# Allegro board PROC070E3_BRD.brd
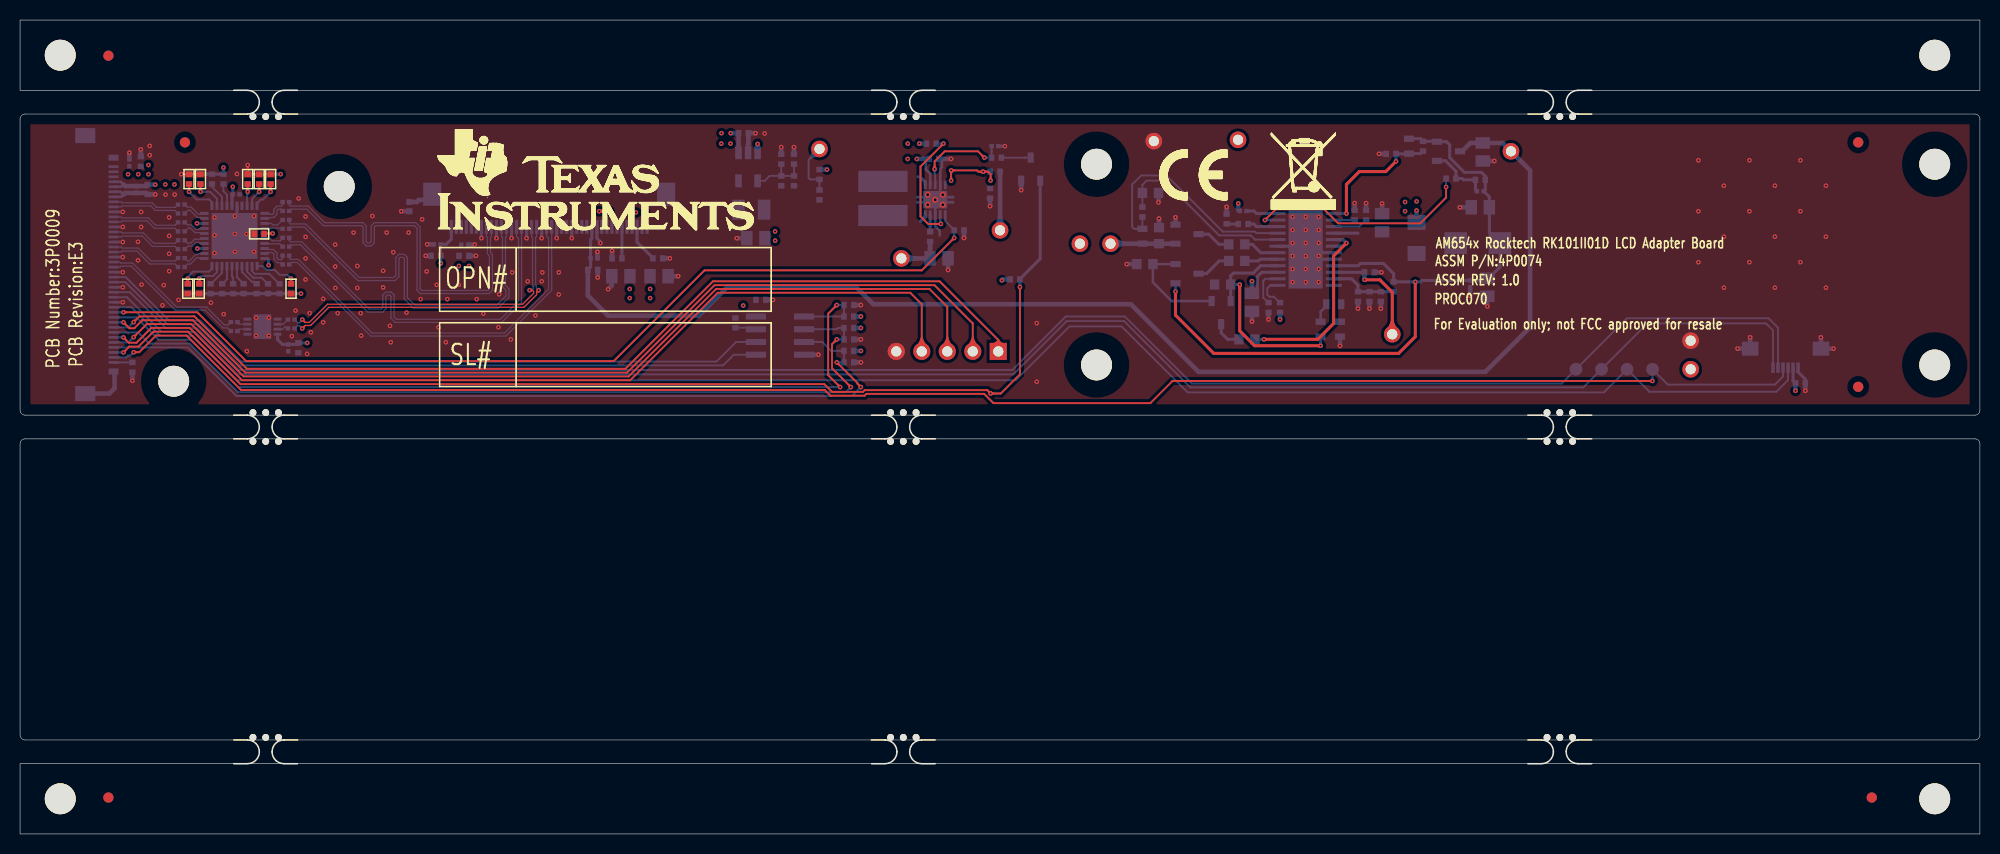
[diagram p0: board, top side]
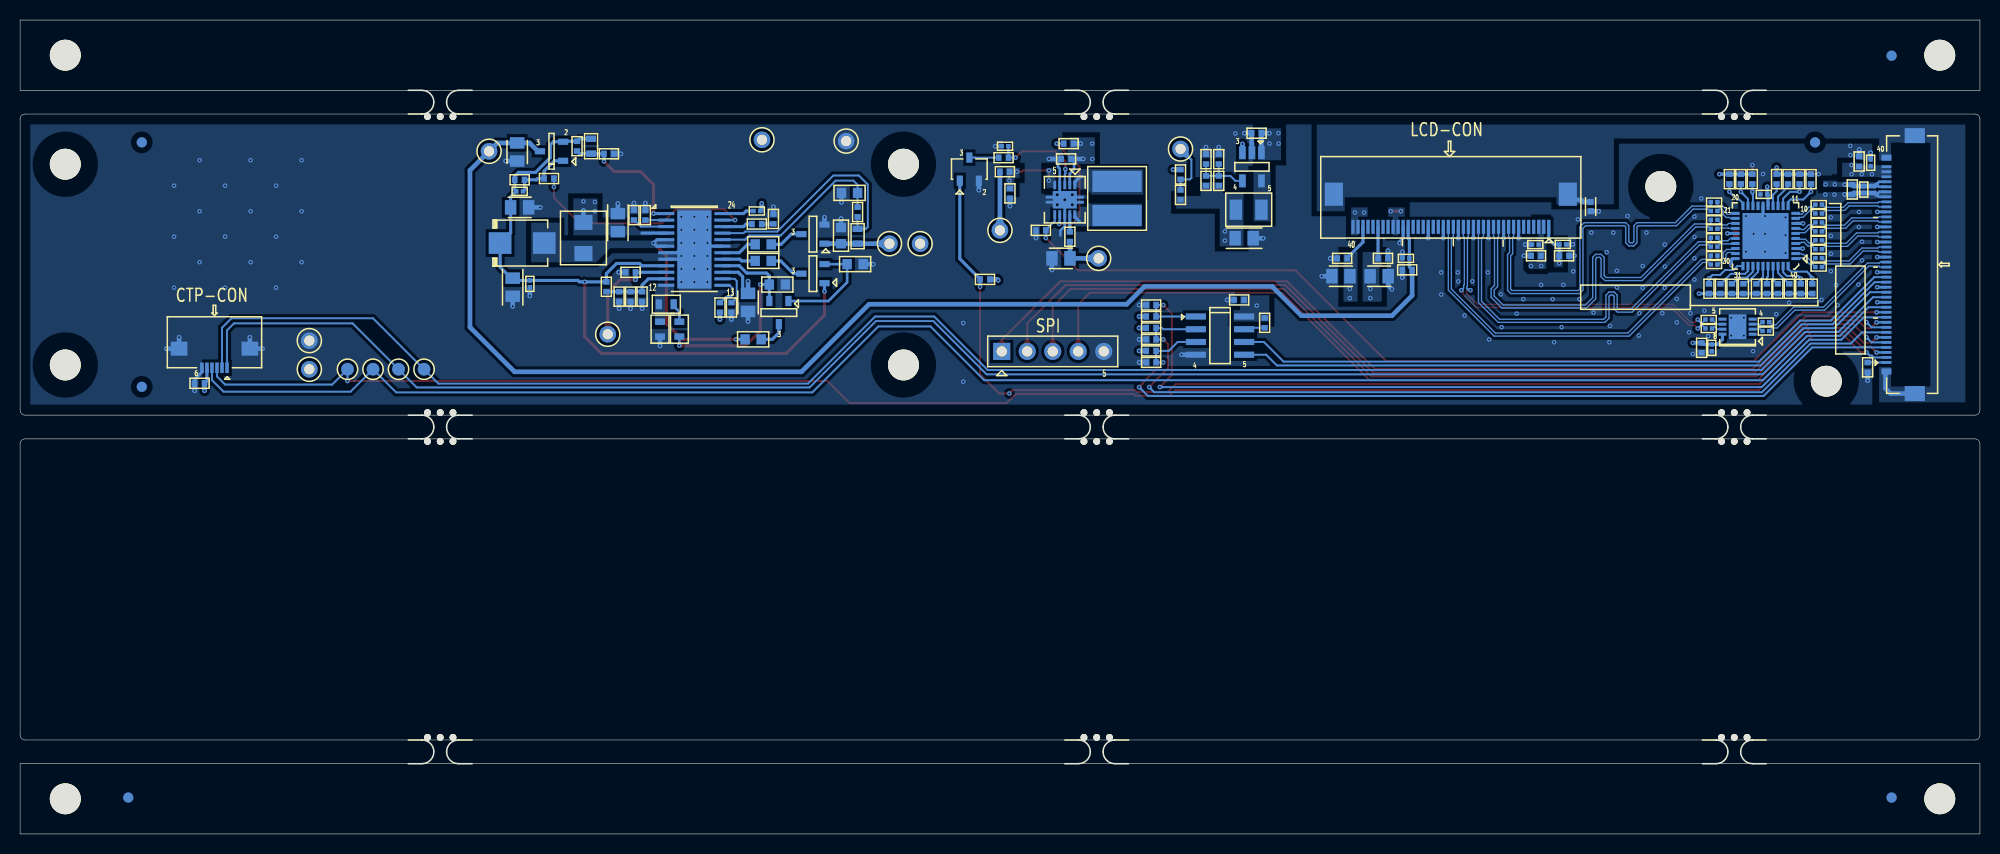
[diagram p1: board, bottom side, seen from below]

Outline 195.18 x 81.09 mm; copper layers: TOP, L02_PWR, L03_GND, BOTTOM. Coordinates in mm from the lower left corner of the outline.
Outline path: 0,81.09 195.18,81.09 195.18,74.09 0,74.09 0,81.09 ; 0,71.22 arc(0.15,71.58) 0.5,71.72 194.68,71.72 arc(195.03,71.58) 195.18,71.22 195.18,42.22 arc(195.03,41.87) 194.68,41.72 0.5,41.72 arc(0.15,41.87) 0,42.22 0,71.22 ; 0,38.86 arc(0.15,39.22) 0.5,39.36 194.68,39.36 arc(195.03,39.22) 195.18,38.86 195.18,9.86 arc(195.03,9.51) 194.68,9.36 0.5,9.36 arc(0.15,9.51) 0,9.86 0,38.86 ; 0,7 195.18,7 195.18,0 0,0 0,7

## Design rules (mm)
net group OLDI0_A0N: nets N18830976 OLDI0_A0N
net group OLDI0_A0N_R: nets N18831716 OLDI0_A0N_R
net group OLDI0_A0P: nets N18830973 OLDI0_A0P
net group OLDI0_A0P_R: nets N18831713 OLDI0_A0P_R
net group OLDI0_A1N: nets N18830970 OLDI0_A1N
net group OLDI0_A1N_R: nets N18831710 OLDI0_A1N_R
net group OLDI0_A1P: nets N18830967 OLDI0_A1P
net group OLDI0_A1P_R: nets N18831707 OLDI0_A1P_R
net group OLDI0_A2N: nets N18830964 OLDI0_A2N
net group OLDI0_A2N_R: nets N18831704 OLDI0_A2N_R
net group OLDI0_A2P: nets N18830961 OLDI0_A2P
net group OLDI0_A2P_R: nets N18831701 OLDI0_A2P_R
net group OLDI0_A3N: nets N18830958 OLDI0_A3N
net group OLDI0_A3N_R: nets N18831698 OLDI0_A3N_R
net group OLDI0_A3P: nets N18830955 OLDI0_A3P
net group OLDI0_A3P_R: nets N18831695 OLDI0_A3P_R
net group OLDI0_CLKN: nets N18844963 OLDI0_CLKN
net group OLDI0_CLKN_R: nets N18844923 OLDI0_CLKN_R
net group OLDI0_CLKP: nets N18844960 OLDI0_CLKP
net group OLDI0_CLKP_R: nets N18844920 OLDI0_CLKP_R

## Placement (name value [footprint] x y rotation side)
C11  1uF  [CAP0402_0-75]  177.3 44.9 0 bottom
C12  1uF  [CAP0805_1-5]  59.83 55.57 180 bottom
C13  0.1uF  [CAP0201_0-5]  41.54 58.74 180 bottom
C14  0.1uF  [CAP0201_0-5]  44.28 58.72 0 bottom
C15  1uF  [CAP0402_0-75]  57.03 56.2 0 bottom
C16  0.1uF  [CAP0402_0-75]  59.45 57.35 180 bottom
C17  0.1uF  [CAP0402_0-75]  63.51 57.35 0 bottom
C18  1uF  [CAP0805_1-5]  63.64 55.57 0 bottom
C19  1uF  [CAP0402_0-75]  41.41 57.6 180 bottom
C20  1uF  [CAP0402_0-75]  44.2 57.6 0 bottom
C21  1uF  [CAP0402_0-75]  73.77 53.21 0 bottom
C22  0.1uF  [CAP0201_0-5]  57.16 57.35 0 bottom
C23  1uF  [CAP0402_0-75]  12.03 67 90 bottom
C24  0.1uF  [CAP0201_0-5]  10.88 66.87 90 bottom
C25  1uF  [CAP0402_0-75]  12.71 64.2 270 bottom
C26  0.1uF  [CAP0201_0-5]  11.57 64.2 270 bottom
C28  4.7uF  [CAP0402_0-75]  91.01 67.25 0 bottom
C29  4.7uF  [CAP0402_0-75]  72.04 69.82 0 bottom
C30  22pF  [CAP0402_0-75]  75.8 65.07 90 bottom
C31  22uF  [CAP0805_1]  73.27 59.35 180 bottom
C32  4.7uF  [CAP0805_1-5]  91.52 57.35 0 bottom
C33  100pF  [CAP0402]  75.8 67.23 90 bottom
C34  1000pF  [CAP0402_0-75]  135.52 53.54 90 bottom
C35  1uF  [CAP0402_0-75]  134.38 53.54 90 bottom
C36  22uF  [CAP0805_1]  135.64 60.9 90 bottom
C37  33pF  [CAP0402]  139.71 68.52 270 bottom
C38  22uF  [CAP0805_1]  146.12 54.47 270 bottom
C39  0.1uF  [CAP0201_0-5]  144.41 54.81 270 bottom
C40  0.1uF  [CAP0201_0-5]  145.43 64.03 180 bottom
C41  1uF  [CAP0805_1-5]  145.67 67.94 270 bottom
C42  1uF  [CAP0805_1-5]  145.42 62.43 180 bottom
C43  0.33uF  [CAP0603]  113.42 59.61 90 bottom
C44  0.33uF  [CAP0603]  121.17 58.74 0 bottom
C45  0.33uF  [CAP0603]  121.17 57.09 180 bottom
C46  0.33uF  [CAP0603]  112.01 56.77 180 bottom
C47  0.1uF  [CAP0201_0-5]  121.8 62.06 0 bottom
C48  1uF  [CAP0805_1-5]  122.68 52.96 270 bottom
C49  1uF  [CAP0402_0-75]  134.38 55.96 0 bottom
C50  22pF  [CAP0402_0-75]  124.33 52.45 90 bottom
C51  470pF  [CAP0402_0-75]  121.8 60.76 180 bottom
C52  0.22uF  [CAP0603]  112.57 63.87 0 bottom
C53  0.047uF  [CAP0402]  134.05 61.65 270 bottom
C54  0.047uF  [CAP0402]  132.9 61.65 270 bottom
C55  0.1uF  [CAP0201_0-5]  21.52 63.72 0 bottom
C56  1uF  [CAP0402_0-75]  23.81 59.78 180 top
C57  0.1uF  [CAP0201_0-5]  26.7 48.43 270 bottom
C58  1uF  [CAP0402_0-75]  27.72 48.43 270 bottom
C59  0.33uF  [CAP0603]  122.17 49.28 180 bottom
C60  0.33uF  [CAP0603]  119.76 54.74 180 bottom
D1  MBRS130LT3  [DIO_SMB]  145.17 58.87 180 bottom
D2  BAT54S  [DIO_SOT23_123]  116.22 59.76 90 bottom
D3  BAT54S  [DIO_SOT23_123]  116.22 55.82 90 bottom
D4  BAT54S  [DIO_SOT23_123]  119.61 51.94 0 bottom
FL1  120E  [EMIFIL_BLM15A_0402_0-6]  38.77 62.5 90 bottom
J4  CON_FLEX_1X40_20720-040  [CON_FLEX1X40_20720-040_S_R_S_2]  6.75 56.72 90 bottom
J9  CON_FLEX_1X6_54550  [CON_FLEX1X6_54550-0671_S_R_S_1-3]  175.82 48.35 0 bottom
J10  CON_FLEX_40X1_FH12A-40S-0.5SH  [CON_FLEX40X1_FH12A_S_R_S]  52.69 64.06 0 bottom
J11  HDR_1X5  [HDR_5X1_100_S_T_11-2]  97.42 48.07 0 bottom
L1  4.7uH  [IND_VLCF5020T_205X210_SMD]  85.93 63.31 0 bottom
L2  4.7uH  [IND_LQH32PN_140X110_SMD_1-7]  72.82 62.2 0 bottom
L3  3.9uH  [IND_ELL4GG_170X170_SMD]  139.07 59.38 270 bottom
NOREF  -  [unnamed]  87.96 8.18 0 top
NOREF#2  -  [#2]  116.03 65.67 0 top
NOREF#3  -  [#2]  0.5 41.72 90 top
NOREF#4  -  [unnamed#3]  183.06 44.55 0 top
NOREF#5  -  [#2]  0.5 39.36 90 top
NOREF#6  -  [unnamed]  153.34 8.18 0 top
NOREF#7  -  [unnamed]  87.96 72.91 180 top
NOREF#8  -  [#2]  116.43 15.16 0 top
NOREF#9  -  [unnamed#3]  183.06 68.9 0 top
NOREF#10  -  [unnamed#4]  87.96 40.54 0 top
NOREF#11  -  [unnamed]  24.46 8.18 0 top
NOREF#12  -  [unnamed#3]  184.4 3.62 0 top
NOREF#13  -  [unnamed#3]  16.42 68.9 0 top
NOREF#14  -  [unnamed]  153.34 72.91 180 top
NOREF#15  -  [#2]  0 71.22 0 top
NOREF#16  -  [#2]  0 0 90 top
NOREF#17  -  [unnamed#3]  8.8 3.62 0 top
NOREF#18  -  [unnamed]  24.46 72.91 180 top
NOREF#19  -  [unnamed#4]  24.46 40.54 0 top
NOREF#20  -  [#2]  -220.46 -73.02 0 top
NOREF#21  -  [unnamed#4]  153.34 40.54 0 top
NOREF#22  -  [unnamed#3]  8.8 77.54 0 top
NOREF#23  -  [#2]  -269.43 -62.64 0 top
NOREF#24  -  [#2]  0 0 90 top
NOREF#25  -  [#2]  27.31 -55.68 0 top
NOREF#26  -  [unnamed#3]  183.06 44.55 180 bottom
NOREF#27  -  [unnamed#3]  107.2 46.72 180 bottom
NOREF#28  -  [unnamed#3]  183.06 68.9 180 bottom
NOREF#29  -  [unnamed#3]  4 77.59 180 bottom
NOREF#30  -  [unnamed#3]  4 3.5 180 bottom
NOREF#31  -  [unnamed#3]  190.68 3.5 180 bottom
NOREF#32  -  [unnamed#3]  16.42 68.9 180 bottom
NOREF#33  -  [unnamed#3]  190.68 66.72 180 bottom
NOREF#34  -  [unnamed#3]  107.2 66.72 180 bottom
NOREF#35  -  [unnamed#3]  190.68 46.72 180 bottom
NOREF#36  -  [unnamed#3]  184.4 3.62 180 bottom
NOREF#37  -  [unnamed#3]  8.8 77.54 180 bottom
NOREF#38  -  [unnamed#3]  190.68 77.59 180 bottom
NOREF#39  -  [unnamed#3]  31.78 64.51 180 bottom
NOREF#40  -  [unnamed#3]  8.8 3.62 180 bottom
NOREF#41  -  [unnamed#3]  15.3 45.1 180 bottom
Q1  BSS138  [TO_SOT23-123]  100.64 66.24 90 bottom
R11  10K_1%  [RES0402_0-5]  82.54 51.55 180 bottom
R12  10K_1%  [RES0402_0-5]  82.54 50.41 180 bottom
R13  10K_1%  [RES0402_0-5]  82.54 48.13 180 bottom
R14  10K_1%  [RES0402_0-5]  71.23 50.92 270 bottom
R15  0E  [RES0402_0-5]  82.54 46.98 0 bottom
R16  0E  [RES0402_0-5]  82.54 49.27 0 bottom
R17  0E  [RES0402_0-5]  82.54 52.7 0 bottom
R18  0E  [RES0402_0-5]  11.18 46.48 90 bottom
R19  0E  [RES0402_0-5]  79.61 63.67 90 bottom
R20  0E  [RES0402_0-5]  79.61 65.7 270 bottom
R21  0E  [RES0402_0-5]  90.63 59.5 270 bottom
R22  806K_1%  [RES0402]  77.07 65.07 90 bottom
R23  10K_1%  [RES0402_0-5]  90.75 68.78 0 bottom
R24  0E  [RES0402_0-5]  97.1 65.98 0 bottom
R25  10E_1%  [RES0402_0-5]  97.23 67.38 0 bottom
R26  200K_1%  [RES0402]  77.07 67.23 90 bottom
R27  10K_1%  [RES0402_0-5]  99.08 55.25 0 bottom
R28  52.3K_1%  [RES0201_0-5]  97.09 68.52 0 bottom
R29  1E_1%  [RES0402]  96.6 63.82 270 bottom
R30  10K_1%  [RES0402_0-5]  93.51 60.14 0 bottom
R31  8.25K_1%  [RES0402]  133.23 53.54 90 bottom
R32  12.1K_1%  [RES0402]  136.79 54.52 90 bottom
R33  604K_1%  [RES0603]  138.31 68.52 270 bottom
R34  510K_1%  [RES0402]  145.43 65.17 180 bottom
R35  97.6K_1%  [RES0402_0-5]  136.54 67.76 180 bottom
R36  576K_1%  [RES0603]  111.77 59.55 90 bottom
R37  100K_1%  [RES0402_0-5]  142.5 65.3 180 bottom
R38  300K_0.5%  [RES0603_0-75]  130.82 52.77 180 bottom
R39  100K_1%  [RES0402_0-5]  111.77 61.96 90 bottom
R40  0E  [RES0402_0-5]  125.48 52.45 90 bottom
R41  22.6K_0.5%  [RES0603_0-75]  131.44 50.29 270 bottom
R42  33K  [RES0402]  120.15 61.27 90 bottom
R48  10K_1%  [RES0402_0-5]  16.7 54.32 90 bottom
R49  10K_1%  [RES0402_0-5]  17.84 54.32 90 bottom
R50  10K_1%  [RES0402_0-5]  16.82 65.24 270 bottom
R51  10K_1%  [RES0402_0-5]  17.97 65.24 270 bottom
R53  10K_1%  [RES0402_0-5]  22.66 65.24 270 bottom
R54  10K_1%  [RES0402_0-5]  16.7 54.32 270 top
R55  10K_1%  [RES0402_0-5]  17.84 54.32 270 top
R56  10K_1%  [RES0402_0-5]  16.82 65.24 90 top
R57  10K_1%  [RES0402_0-5]  17.97 65.24 90 top
R59  10K_1%  [RES0402_0-5]  22.66 65.24 90 top
R60  10K_1%  [RES0402_0-5]  23.81 65.24 270 bottom
R61  10K_1%  [RES0402_0-5]  23.81 65.24 90 top
R62  10K_1%  [RES0402_0-5]  24.95 65.24 270 bottom
R63  10K_1%  [RES0402_0-5]  24.95 65.24 90 top
R64  10K_1%  [RES0402_0-5]  26.98 54.32 90 bottom
R65  10K_1%  [RES0402_0-5]  26.98 54.32 270 top
R66  10K_1%  [RES0402_0-5]  21.22 54.32 90 bottom
R67  10K_1%  [RES0402_0-5]  19.11 65.24 270 bottom
R68  10K_1%  [RES0402_0-5]  20.12 54.32 90 bottom
R69  10K_1%  [RES0402_0-5]  20.25 65.24 270 bottom
R70  10K_1%  [RES0402_0-5]  25.84 54.32 90 bottom
R71  10K_1%  [RES0402_0-5]  24.7 54.32 90 bottom
R72  10K_1%  [RES0402_0-5]  23.55 54.32 90 bottom
R73  10K_1%  [RES0402_0-5]  22.26 54.32 90 bottom
R74  10K_1%  [RES0402_0-5]  18.98 54.32 90 bottom
R95  0E  [RES0201_0-5]  16.06 56.48 0 bottom
R96  0E  [RES0201_0-5]  16.06 57.37 0 bottom
R97  0E  [RES0201_0-5]  16.06 58.26 0 bottom
R98  0E  [RES0201_0-5]  16.06 59.15 0 bottom
R99  0E  [RES0201_0-5]  16.06 60.04 0 bottom
R100  0E  [RES0201_0-5]  16.06 60.93 0 bottom
R101  0E  [RES0201_0-5]  16.06 61.82 0 bottom
R102  0E  [RES0201_0-5]  16.06 62.7 0 bottom
R103  0E  [RES0201_0-5]  26.47 56.74 0 bottom
R104  0E  [RES0201_0-5]  26.47 57.62 0 bottom
R105  0E  [RES0201_0-5]  26.47 58.51 0 bottom
R106  0E  [RES0201_0-5]  26.47 59.4 0 bottom
R107  0E  [RES0201_0-5]  26.47 60.29 0 bottom
R108  0E  [RES0201_0-5]  26.47 61.18 0 bottom
R109  0E  [RES0201_0-5]  26.47 62.96 0 bottom
R110  0E  [RES0201_0-5]  26.47 62.07 0 bottom
R111  0E  [RES0201_0-5]  21.32 50.11 0 bottom
R112  0E  [RES0201_0-5]  21.32 51 0 bottom
R113  0E  [RES0201_0-5]  27.01 50.36 0 bottom
R114  0E  [RES0201_0-5]  27.01 51.25 0 bottom
R115  86.6K_0.5%  [RES0603_0-75]  129.52 50.29 270 bottom
TP6  THRU HOLE  [TP_40X65]  148.47 68.01 180 bottom
TP7  THRU HOLE  [TP_40X65]  79.61 68.24 270 bottom
TP8  THRU HOLE  [TP_40X65]  136.65 49.78 180 bottom
TP9  THRU HOLE  [TP_40X65]  108.6 58.81 180 bottom
TP10  THRU HOLE  [TP_40X65]  105.55 58.81 180 bottom
TP27  SMD  [TP50_SMD]  157.49 46.3 180 bottom
TP28  SMD  [TP50_SMD]  154.95 46.3 180 bottom
TP29  SMD  [TP50_SMD]  162.57 46.3 180 bottom
TP30  SMD  [TP50_SMD]  160.03 46.3 180 bottom
TP32  THRU HOLE  [TP_40X65]  87.77 57.35 180 bottom
TP33  THRU HOLE  [TP_40X65]  97.59 60.14 180 bottom
TP34  THRU HOLE  [TP_40X65]  166.37 46.3 180 bottom
TP35  THRU HOLE  [TP_40X65]  121.29 69.16 180 bottom
TP36  THRU HOLE  [TP_40X65]  112.91 69.03 180 bottom
TP37  THRU HOLE  [TP_40X65]  166.37 49.15 180 bottom
U1  CAT24C256WI-GT3  [SOIC8_1-8]  75.68 49.65 180 bottom
U2  LM3670MF-ADJ  [SOT23-5_1-5]  72.5 66.47 270 bottom
U3  TPS61081DRCT  [SON10_19-68_125X125]  91.14 63.19 270 bottom
U4  SI2301CDS-T1-GE3  [SOT23-123]  142.25 68.01 0 bottom
U5  TPS65150PWP  [HTSSOP24_TPS65150_180X310_1-2]  128.03 58.23 180 bottom
U6  DS25BR440TSQ  [QFN40_19-68_240X240_0-8]  21.35 59.58 0 bottom
U7  DS10BR150TSD  [DFN8_19-68_120X120_0-8]  24.14 50.54 0 bottom

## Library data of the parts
C11-C26 C28-C60 = CAP
D1 = DIODE_SCHOTTKY
D2-D4 = DIODE_BAT54S_SOT23-123
FL1 = EMIFILTER_IND
J4 = CON_FLEX_40X1_SH4
J9 = CON_FLEX_6X1_SH2
J10 = CON_FLEX_40X1_FH12A-40S-0.5SH
J11 = HEADER_5X1
L1-L3 = INDUCTOR
Q1 = MOSFET_BSS138
R11-R42 R48-R51 R53-R57 R59-R74 R115 = RESISTOR
R95-R114 = RESISTOR: signal model: RESISTOR_RES0201_0-5_0E_0E
TP6-TP10 TP27-TP30 TP32-TP37 = TESTPOINT
U1 = CAT24C256WI-GT3_SOIC8
U2 = LM3670MF-ADJ_SOT23-5
U3 = TPS61081DRCT_SON10
U4 = SI2301CDS_SOT23-3
U5 = TPS65150PWP_TSSOP24
U6 = DS25BR440TSQ_WQFN40
U7 = DS10BR150TSD_WSON8

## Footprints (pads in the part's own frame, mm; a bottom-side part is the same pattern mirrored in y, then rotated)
CAP0201_0-5
  rect 0.457x0.432 smd: 1(-0.34,0) 2(0.34,0)
CAP0402
  rect 0.559x0.635 smd: 1(-0.49,0) 2(0.49,0)
CAP0402_0-75
  rect 0.559x0.635 smd: 1(-0.49,0) 2(0.49,0)
CAP0603
  rect 0.94x1.016 smd: 1(-0.8,0) 2(0.8,0)
CAP0805_1
  rect 1.143x1.448 smd: 1(-0.9,0) 2(0.9,0)
CAP0805_1-5
  rect 1.143x1.448 smd: 1(-0.9,0) 2(0.9,0)
CON_FLEX1X6_54550-0671_S_R_S_1-3
  rect 0.356x1.041 smd: 1(-1.25,1.901) 2(-0.75,1.901) 3(-0.25,1.901) 4(0.25,1.901) 5(0.75,1.901) 6(1.25,1.901)
  rect 1.651x1.397 smd: SH1(-3.525,0.001) SH2(3.525,0.001)
CON_FLEX1X40_20720-040_S_R_S_2
  rect 0.279x0.991 smd: 1(-9.75,2.556) 2(-9.25,2.556) 3(-8.75,2.556) 4(-8.25,2.556) 5(-7.75,2.556) 6(-7.25,2.556) 7(-6.75,2.556) 8(-6.25,2.556) 9(-5.75,2.556) 10(-5.25,2.556) 11(-4.75,2.556) 12(-4.25,2.556) 13(-3.75,2.556) 14(-3.25,2.556) 15(-2.75,2.556) 16(-2.25,2.556) 17(-1.75,2.556) 18(-1.25,2.556) 19(-0.75,2.556) 20(-0.25,2.556) 21(0.25,2.556) 22(0.75,2.556) 23(1.25,2.556) 24(1.75,2.556) 25(2.25,2.556) 26(2.75,2.556) 27(3.25,2.556) 28(3.75,2.556) 29(4.25,2.556) 30(4.75,2.556) 31(5.25,2.556) 32(5.75,2.556) 33(6.25,2.556) 34(6.75,2.556) 35(7.25,2.556) 36(7.75,2.556) 37(8.25,2.556) 38(8.75,2.556) 39(9.25,2.556) 40(9.75,2.556)
  rect 0.61x0.991 smd: SH1(-10.65,2.556) SH2(10.65,2.556)
  rect 1.499x2.007 smd: SH3(-12.85,-0.264) SH4(12.85,-0.264)
CON_FLEX40X1_FH12A_S_R_S
  rect 0.33x1.397 smd: 1(-9.75,3.575) 2(-9.25,3.575) 3(-8.75,3.575) 4(-8.25,3.575) 5(-7.75,3.575) 6(-7.25,3.575) 7(-6.75,3.575) 8(-6.25,3.575) 9(-5.75,3.575) 10(-5.25,3.575) 11(-4.75,3.575) 12(-4.25,3.575) 13(-3.75,3.575) 14(-3.25,3.575) 15(-2.75,3.575) 16(-2.25,3.575) 17(-1.75,3.575) 18(-1.25,3.575) 19(-0.75,3.575) 20(-0.25,3.575) 21(0.25,3.575) 22(0.75,3.575) 23(1.25,3.575) 24(1.75,3.575) 25(2.25,3.575) 26(2.75,3.575) 27(3.25,3.575) 28(3.75,3.575) 29(4.25,3.575) 30(4.75,3.575) 31(5.25,3.575) 32(5.75,3.575) 33(6.25,3.575) 34(6.75,3.575) 35(7.25,3.575) 36(7.75,3.575) 37(8.25,3.575) 38(8.75,3.575) 39(9.25,3.575) 40(9.75,3.575)
  rect 1.803x2.311 smd: 41(-11.65,0.325) 42(11.65,0.325)
DFN8_19-68_120X120_0-8
  rect 0.787x0.305 smd: 1(-1.5,0.75) 2(-1.5,0.25) 3(-1.5,-0.25) 4(-1.5,-0.75) 5(1.5,-0.75) 6(1.5,-0.25) 7(1.5,0.25) 8(1.5,0.75)
  rect 1.753x2.464 smd: 9(0,0)
DIO_SMB
  rect 2.261x2.159 smd: 1(-2.2,0) 2(2.2,0)
DIO_SOT23_123
  rect 0.61x1.016 smd: 1(-0.95,-1.15) 2(0.95,-1.15) 3(0,1.15)
EMIFIL_BLM15A_0402_0-6
  rect 0.61x0.61 smd: 1(-0.46,0) 2(0.46,0)
HDR_5X1_100_S_T_11-2
  rect 1.702x1.702 hole 1.016: 1(0,0)
  round 1.702 hole 1.016: 2(-2.54,0) 3(-5.08,0) 4(-7.62,0) 5(-10.16,0)
HTSSOP24_TPS65150_180X310_1-2
  rect 1.6x0.305 smd: 1(-2.8,3.575) 2(-2.8,2.925) 3(-2.8,2.275) 4(-2.8,1.625) 5(-2.8,0.975) 6(-2.8,0.325) 7(-2.8,-0.325) 8(-2.8,-0.975) 9(-2.8,-1.625) 10(-2.8,-2.275) 11(-2.8,-2.925) 12(-2.8,-3.575) 13(2.8,-3.575) 14(2.8,-2.925) 15(2.8,-2.275) 16(2.8,-1.625) 17(2.8,-0.975) 18(2.8,-0.325) 19(2.8,0.325) 20(2.8,0.975) 21(2.8,1.625) 22(2.8,2.275) 23(2.8,2.925) 24(2.8,3.575)
  rect 3.404x7.798 smd: 25(0,0)
IND_ELL4GG_170X170_SMD
  rect 1.499x1.803 smd: 1(-1.55,0) 2(1.55,0)
IND_LQH32PN_140X110_SMD_1-7
  rect 1.245x2.007 smd: 1(-1.275,0) 2(1.275,0)
IND_VLCF5020T_205X210_SMD
  rect 4.902x2.108 smd: 1(0,-1.7) 2(0,1.7)
QFN40_19-68_240X240_0-8
  rect 0.838x0.305 smd: 1(-3,2.25) 2(-3,1.75) 3(-3,1.25) 4(-3,0.75) 5(-3,0.25) 6(-3,-0.25) 7(-3,-0.75) 8(-3,-1.25) 9(-3,-1.75) 10(-3,-2.25) 21(3,-2.25) 22(3,-1.75) 23(3,-1.25) 24(3,-0.75) 25(3,-0.25) 26(3,0.25) 27(3,0.75) 28(3,1.25) 29(3,1.75) 30(3,2.25)
  rect 0.305x0.838 smd: 11(-2.25,-3) 12(-1.75,-3) 13(-1.25,-3) 14(-0.75,-3) 15(-0.25,-3) 16(0.25,-3) 17(0.75,-3) 18(1.25,-3) 19(1.75,-3) 20(2.25,-3) 31(2.25,3) 32(1.75,3) 33(1.25,3) 34(0.75,3) 35(0.25,3) 36(-0.25,3) 37(-0.75,3) 38(-1.25,3) 39(-1.75,3) 40(-2.25,3)
  rect 4.572x4.572 smd: 41(0,0)
RES0201_0-5
  rect 0.457x0.432 smd: 1(-0.33,0) 2(0.33,0)
RES0402
  rect 0.559x0.635 smd: 1(-0.49,0) 2(0.49,0)
RES0402_0-5
  rect 0.559x0.635 smd: 1(-0.49,0) 2(0.49,0)
RES0603
  rect 0.635x0.991 smd: 1(-0.74,0) 2(0.74,0)
RES0603_0-75
  rect 0.635x0.991 smd: 1(-0.74,0) 2(0.74,0)
SOIC8_1-8
  rect 2.007x0.61 smd: 1(-2.4,1.905) 2(-2.4,0.635) 3(-2.4,-0.635) 4(-2.4,-1.905) 5(2.4,-1.905) 6(2.4,-0.635) 7(2.4,0.635) 8(2.4,1.905)
SON10_19-68_125X125
  rect 0.864x0.279 smd: 1(-1.475,1) 2(-1.475,0.5) 3(-1.475,0) 4(-1.475,-0.5) 5(-1.475,-1) 6(1.475,-1) 7(1.475,-0.5) 8(1.475,0) 9(1.475,0.5) 10(1.475,1)
  custom 0.435x0.435 smd: 11(0,0)
SOT23-5_1-5
  rect 1.295x0.66 smd: 1(-1.4,0.95) 2(-1.4,0) 3(-1.4,-0.95) 4(1.4,-0.95) 5(1.4,0.95)
SOT23-123
  rect 1.016x0.61 smd: 1(-1.15,0.95) 2(-1.15,-0.95) 3(1.15,0)
TO_SOT23-123
  rect 1.016x0.61 smd: 1(-1.15,0.95) 2(-1.15,-0.95) 3(1.15,0)
TP50_SMD
  round 1.27 smd: 1(0,0)
TP_40X65
  round 1.651 hole 1.016: 1(0,0)
unnamed
  round 0.686 hole 0.813 unplated: (-1.27,1.435) (0,1.435) (1.27,1.435)
unnamed#3
  round 1.016 smd: (0,0)
unnamed#4
  round 0.686 hole 0.813 unplated: (-1.27,1.435) (-1.27,-1.435) (0,1.435) (0,-1.435) (1.27,1.435) (1.27,-1.435)

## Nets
AVDD: C15.1 C22.1 C41.1 J10.29 TP6.1(TP) U4.3(D)
DGND: C11.2 C12.2 C13.2 C14.2 C15.2 C16.2 C17.2 C18.2 C19.2 C20.2 C21.2 C22.2 C23.2 C24.2 C25.2 C26.2 C28.2 C29.2 C31.2 C32.2 C33.2 C34.1 C35.1 C36.2 C38.2 C39.2 C41.2 C42.2 C43.2 C46.2 C48.2 C49.2 C50.1 C52.2 C53.1 C54.1 C55.2 C56.2 C57.2 C58.2 C60.2 D2.2(K1) FL1.1 J4.13 J4.16 J4.19 J4.22 J4.25 J4.28 J4.31 J4.34 J4.35 J9.6 J9.SH1 J9.SH2 J10.7 J10.10 J10.13 J10.16 J10.19 J10.22 J10.25 J10.30 J11.5 Q1.2(S) R15.2 R16.2 R17.2 R18.1 R26.2 R28.2 R29.2 R30.2 R31.1 R35.2 R41.2 R42.2 R54.2 R55.2 R56.2 R57.2 R59.2 R61.2 R63.2 R65.2 TP36.1(TP) TP37.1(TP) U1.4(VSS) U2.2(GND) U3.4(GND) U3.8(PGND) U3.11(PAD) U5.7(PGND1) U5.8(PGND2) U5.19(GND) U5.25(EP) U6.16(GND) U6.41(EP) U7.9(GND)
VCC3V3: C11.1 C21.1 C25.1 C26.1 C55.1 C56.1 C57.1 C58.1 J4.36 J4.37 J9.5 R11.1 R12.1 R13.1 R14.1 R27.1 R40.1 R48.1 R49.1 R50.1 R51.1 R53.1 R60.1 R62.1 R64.1 R66.1 R67.1 R68.1 R69.1 R70.1 R71.1 R72.1 R73.1 R74.1 TP34.1(TP) U1.8(VCC) U6.3(VDD#3) U6.8(VDD#8) U6.15(VDD#15) U6.25(VDD#25) U6.30(VDD#30) U7.8(VCC)
VCC_5V0: C23.1 C24.1 C28.1 C29.1 C36.1 C47.1 J4.38 J4.39 J4.40 L3.1 R20.1 R23.1 TP35.1(TP) U2.1(VIN) U2.3(EN) U3.2(VIN) U5.4(VIN)
VDD_2V5: C14.1 C20.1 C30.1 C31.1 J10.2 J10.3 L2.2 R19.1 R22.1
VDD_OPT: R19.2 R20.2 TP7.1(TP)
ADJ: C50.2 U5.14(ADJ)
BKLT_L: L1.1 U3.1(L)
BKLT_SW: L1.2 U3.10(SW)
BRDID_EEPROM_A0: J4.10 R11.2 R17.1 U1.1(A0)
BRDID_EEPROM_A1: J4.7 R12.2 R16.1 U1.2(A1)
BRDID_EEPROM_A2: J4.4 R13.2 R15.1 U1.3(A2)
COMP: C51.1 U5.22(COMP)
CPI: C60.1 D4.2(K1) R115.2 U5.16(CPI)
CPI_1: C46.1 D3.2(K1) D4.1(A2)
CTRL: R40.2 U5.13(CTRL)
DLY1: C54.2 U5.2(DLY1)
DLY2: C53.2 U5.3(DLY2)
ECAP0_IN_APWM0_OUT: J4.3 Q1.1(G) R27.2
EEPROM_WP: R14.2 U1.7(WP)
EQ0: R48.2 R54.1 U6.40(EQ0)
EQ1: R49.2 R55.1 U6.39(EQ1)
EQ2: R50.2 R56.1 U6.11(EQ2)
EQ3: R51.2 R57.1 U6.12(EQ3)
FBN: R36.2 R39.1 U5.21(FBN)
FDLY: C47.2 U5.24(FDLY)
GD: R37.2 U5.23(GD)
LCD_BACKLIGHT_EN: J4.11 R30.1 U3.6(EN)
LCD_BRD_DET: J4.1 R18.2
LCD_BRD_TOUCH_INT: J4.12 J9.4 TP30.1(TP)
LCD_BRD_TOUCH_RESETN: J4.2 J9.3 TP29.1(TP)
LCD_SHIELD: FL1.2 J4.SH1 J4.SH2 J4.SH3 J4.SH4 J10.41 J10.42
LED+: C32.1 J10.39 J10.40 R21.2 TP32.1(TP)
LED-: J10.31 J10.32 R24.2 TP33.1(TP)
LOSN0: R69.2 U6.14(L\O\S\0\)
LOSN1: R68.2 U6.37(L\O\S\1\)
LOSN2: R66.2 U6.36(L\O\S\2\)
LOSN3: R67.2 U6.13(L\O\S\3\)
OLDI0_A0N: J4.33 R102.1
OLDI0_A0N_R: J10.8 R109.2
OLDI0_A0P: J4.32 R101.1
OLDI0_A0P_R: J10.9 R110.2
OLDI0_A1N: J4.30 R100.1
OLDI0_A1N_R: J10.11 R108.2
OLDI0_A1P: J4.29 R99.1
OLDI0_A1P_R: J10.12 R107.2
OLDI0_A2N: J4.27 R98.1
OLDI0_A2N_R: J10.14 R106.2
OLDI0_A2P: J4.26 R97.1
OLDI0_A2P_R: J10.15 R105.2
OLDI0_A3N: J4.24 R96.1
OLDI0_A3N_R: J10.20 R104.2
OLDI0_A3P: J4.23 R95.1
OLDI0_A3P_R: J10.21 R103.2
OLDI0_CLKN: J4.21 R112.1
OLDI0_CLKN_R: J10.17 R114.2
OLDI0_CLKP: J4.20 R111.1
OLDI0_CLKP_R: J10.18 R113.2
PE0: R64.2 R65.1 U6.31(PE0)
PE1: R62.2 R63.1 U6.20(PE1)
PE2: R60.2 R61.1 U6.19(PE2)
PE3: R53.2 R59.1 U6.18(PE3)
PWDNN: R74.2 U6.38(P\W\D\N\)
PWDNN0: R73.2 U6.35(P\W\D\N\0\)
PWDNN1: R72.2 U6.34(P\W\D\N\1\)
PWDNN2: R71.2 U6.33(P\W\D\N\2\)
PWDNN3: R70.2 U6.32(P\W\D\N\3\)
REF: C52.1 R39.2 U5.20(REF)
SOC_I2C1_SCL: J4.15 J9.2 TP28.1(TP)
SOC_I2C1_SDA: J4.14 J9.1 TP27.1(TP)
SOC_SPI1_CLK: J4.9 J11.2
SOC_SPI1_CS0: J4.8 J11.1
SOC_SPI1_MISO: J4.5 J11.3
SOC_SPI1_MOSI: J4.6 J11.4
SOC_WKUP_SCL: J4.18 U1.6(SCL)
SOC_WKUP_SDA: J4.17 U1.5(SDA)
SW: C59.1 D1.2(ANODE) L3.2 U5.5(SW1) U5.6(SW2)
VCOM: C13.1 C19.1 C49.1 J10.1 TP8.1(TP) U5.10(VCOM)
VGH: C17.1 C18.1 C48.1 J10.38 TP10.1(TP) U5.15(VGH)
VGL: C12.1 C16.1 C43.1 D2.1(A2) J10.35 R36.1 TP9.1(TP)
N18700915: R21.1 U3.9(OUT)
N18700972: R24.1 R29.1 U3.5(FB)
N18700978: R25.1 R28.1 U3.3(SS)
N18701008: Q1.3(D) R25.2
N18701075: R23.2 U3.7(FSW)
N18704134: C37.1 C38.1 C39.1 C40.1 C42.1 D1.1(CATHODE) D3.1(A2) R32.2 R33.1 R34.1 U4.2(S) U5.9(SUP)
N18704138: C40.2 R34.2 R37.1 U4.1(G)
N18704166: C37.2 R33.2 R35.1 U5.1(FB)
N18704218: C44.1 D2.3(A1/K2)
N18704228: C45.2 D3.3(A1/K2)
N18704232: R38.1 R41.1 U5.12(FBP)
N18704253: C44.2 U5.18(DRVN)
N18704306: C34.2 C35.2 R31.2 R32.1 U5.11(IN)
N18704451: C45.1 U5.17(DRVP)
N18706570: C51.2 R42.1
N18754754: L2.1 U2.5(SW)
N18754783: C30.2 C33.1 R22.2 R26.1 U2.4(FB)
N18830955: R95.2 U6.1(IN0+)
N18830958: R96.2 U6.2(IN0-)
N18830961: R97.2 U6.4(IN1+)
N18830964: R98.2 U6.5(IN1-)
N18830967: R99.2 U6.6(IN2+)
N18830970: R100.2 U6.7(IN2-)
N18830973: R101.2 U6.9(IN3+)
N18830976: R102.2 U6.10(IN3-)
N18831695: R103.1 U6.29(OUT0+)
N18831698: R104.1 U6.28(OUT0-)
N18831701: R105.1 U6.27(OUT1+)
N18831704: R106.1 U6.26(OUT1-)
N18831707: R107.1 U6.24(OUT2+)
N18831710: R108.1 U6.23(OUT2-)
N18831713: R110.1 U6.22(OUT3+)
N18831716: R109.1 U6.21(OUT3-)
N18844920: R113.1 U7.7(OUT+)
N18844923: R114.1 U7.6(OUT-)
N18844960: R111.2 U7.2(IN+)
N18844963: R112.2 U7.3(IN-)
N18857919: R38.2 R115.1
N18858160: C59.2 D4.3(A1/K2)

Pads without a net: J10 4 5 6 23 24 26 27 28 33 34 36 37; U6 17; U7 1 4 5

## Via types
v1: diameter 0.457, hole 0.203, TOP to BOTTOM, 294 vias
v2: diameter 0.61, hole 0.305, TOP to BOTTOM, 5 vias

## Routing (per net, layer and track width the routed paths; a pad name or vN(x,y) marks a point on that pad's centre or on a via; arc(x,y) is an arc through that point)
AVDD: length 132.3
  BOTTOM w0.305: J10.29 56.94,59.34 56.82,59.23 C22.1 56.82,56.48 C15.1
  BOTTOM w0.457: C15.1 56.54,53.64 58.56,51.63 67.57,51.63 70.49,54.55 83.19,54.55 84.97,52.77 110.63,52.77 117.36,46.04 145.93,46.04 150.38,50.49 150.38,66.11 TP6.1 147.64,68.84 C41.1 144.44,68.84 143.6,68.01 U4.3
DGND: length 89.2
  TOP w0.191: R57.2 R56.2 v1(16.06,65.73) ; R59.2 v1(22.66,66.64)
  BOTTOM w0.254: 91.58,59.63 91.58,60.11 91.14,60.55 U3.8 v2(91.14,63.19) ; J4.31 v1(10.24,61.97) ; J4.22 v1(10.24,57.47) ; 91.81,67.25 91.81,66.44 91.64,66.27 U3.4 91.64,63.94 v2(91.89,63.69) ; J4.13 v1(10.24,52.97) ; J4.19 v1(10.24,55.97) ; J4.16 v1(10.24,54.47) ; J4.34 10.07,63.47 10.3,63.7 10.02,63.97 J4.35 ; J4.25 v1(10.24,58.97) ; J4.28 v1(10.24,60.47)
  BOTTOM w0.305: U5.19 126.4,58.56 v1(126.73,58.88) ; v1(129.33,58.88) 129.33,58.35 129.77,57.91 U5.7 ; J10.22 v1(53.44,59.36) ; v1(57.79,58.87) 57.79,59 57.44,59.35 J10.30 ; J10.16 v1(50.44,59.36) ; R28.2 v1(98.08,68.52) ; J10.10 v1(47.44,59.36) ; J10.7 v1(45.94,59.36) ; C11.2 177.79,45.3 177.07,46.02 J9.6 ; J10.25 v1(54.94,59.36) ; 21.75,60.8 21.6,60.96 U6.16 ; v1(129.33,57.58) 129.65,57.26 U5.8 ; J10.13 v1(48.94,59.36) ; J10.19 v1(51.94,59.36)
  BOTTOM w0.457: C48.2 v1(122.68,51.06) ; R41.2 v1(131.44,48.62) ; v1(171.03,48.35) J9.SH1 v1(172.29,49.48) ; R29.2 v1(96.6,62.55) ; Q1.2 v1(99.69,64.15) ; v1(13.47,63.71) C25.2 12.56,63.86 C26.2 10.46,63.86 10.3,63.7 ; C12.2 58.93,54.64 v1(58.56,54.27) ; R30.2 v1(94,59.38) ; R42.2 v1(120.15,62.47) ; C38.2 v1(146.12,52.57) ; R18.1 v1(11.18,45.15) ; R16.2 v1(83.74,49.27) ; v1(92.71,67.25) 91.81,67.25 ; C22.2 v1(57.5,57.99) ; C54.1 v1(132.9,62.85) ; C23.2 v1(12.03,68.2) ; C21.2 v1(74.97,53.21) ; C11.2 v1(177.79,44.15) ; C52.2 v1(113.37,62.93) ; C41.2 v1(146.82,67.05) ; C18.2 v1(65.54,55.57) ; U1.4 v1(79.51,47.74) ; C16.2 v1(58.96,58.11) ; C33.2 v1(75.8,68.43) ; C42.2 v1(143.38,62.43) ; C17.2 v1(64.71,57.35) ; 72.5,67.77 U2.2 72.5,68.74 72.53,68.77 C29.2 v1(73.24,69.82) ; v1(179.34,49.48) J9.SH2 v1(180.6,48.35) ; C31.2 v1(71.37,59.35) ; R26.2 v1(77.07,68.43) ; C43.2 v1(113.42,61.31) ; C13.2 v1(40.54,58.74) ; D2.2 v1(115.07,61.44) ; C34.1 v1(135.52,52.33) ; R15.2 v1(83.74,46.98) ; C24.2 v1(10.88,67.87) ; C35.1 v1(134.38,52.33) ; C32.2 v1(92.42,56.19) ; C46.2 v1(110.21,56.77) ; R17.2 v1(83.74,52.7) ; C20.2 v1(45.41,57.6) ; C49.2 v1(135.58,55.96) ; C15.2 v1(57.52,55.44) ; C36.2 v1(135.64,62.8) ; C19.2 v1(40.39,57.6) ; R31.1 v1(133.23,52.33) ; FL1.1 v1(37.96,62.04) ; 144.41,54.32 v1(144.41,53.6) ; R35.2 v1(135.33,67.76) ; C50.1 v1(124.33,51.25) ; C14.2 v1(45.28,58.72) ; C53.1 v1(134.05,62.85)
  vias: v1(11.74,59) v1(11.74,57.14) v1(12.05,61.97) v1(12.05,60.47) v1(12.1,54.73) v1(12.91,68.55) v1(12.91,67.63) v1(14.18,52.67) v1(14.31,54.68) v1(14.49,63.7) v1(14.84,61.43) v1(14.84,59.58) v1(14.84,57.8) v1(14.84,56.08) v1(15.4,63.7) v1(15.78,53.21) v1(19.01,52.93) v1(19.36,61.43) v1(19.36,59.66) v1(19.36,57.88) v1(20.28,51.78) v1(21.39,61.56) v1(21.39,59.78) v1(21.39,58.01) v1(21.6,65.75) v1(22.54,59.78) v1(22.59,48.1) v1(23.3,61.56) v1(23.3,58.01) v1(23.5,51.43) v1(23.5,49.65) v1(24.77,51.43) v1(24.77,49.65) v1(27.06,49.6) v1(27.44,52.14) v1(27.74,63.31) v1(28.43,61.51) v1(28.43,59.48) v1(28.43,57.35) v1(28.43,55.24) v1(28.58,47.82) v1(28.84,51.88) v1(28.96,49.98) v1(30.18,53.31) v1(30.18,50.97) v1(31.38,58.72) v1(31.38,56.53) v1(31.4,54.4) v1(31.63,51.88) v1(33.21,59.91) v1(33.59,56.58) v1(33.59,54.4) v1(33.92,51.88) v1(33.97,49.65) v1(35.09,61.56) v1(36.15,56.1) v1(36.15,54.45) v1(36.51,59.91) v1(36.84,50.61) v1(36.91,48.99) v1(37.17,57.95) v1(38.49,51.94) v1(38.69,59.91) v1(39.89,53.28) v1(40.04,61.23) v1(40.5,56.05) v1(41.49,54.7) v1(41.66,50.49) v1(42.4,48.99) v1(42.55,53.28) v1(43.7,54.7) v1(45.47,53.28) v1(46.13,51.83) v1(47.63,50.49) v1(47.71,53.76) v1(48.88,49.27) v1(49,55.95) v1(50.55,55.06) v1(51.32,51.66) v1(52,55.95) v1(51.95,55.06) v1(53.65,55.95) v1(53.65,53.74) v1(74.15,69.79) v1(101.25,50.89) v1(101.25,45.05) v1(126.73,61.48) v1(126.73,60.18) v1(126.73,57.58) v1(126.73,56.28) v1(126.73,54.98) v1(128.03,61.48) v1(128.03,60.18) v1(128.03,58.88) v1(128.03,57.58) v1(128.03,56.28) v1(128.03,54.98) v1(129.33,61.48) v1(129.33,60.18) v1(129.33,56.28) v1(129.33,54.98) v1(167.14,67.12) v1(167.14,62.04) v1(167.14,56.96) v1(169.68,64.58) v1(169.68,59.5) v1(169.68,54.42) v1(172.22,67.12) v1(172.22,62.04) v1(172.22,56.96) v1(174.76,64.58) v1(174.76,59.5) v1(174.76,54.42) v1(177.3,67.12) v1(177.3,62.04) v1(177.3,56.96) v1(179.84,64.58) v1(179.84,59.5) v1(179.84,54.42) v2(90.39,63.69) v2(90.39,62.69) v2(91.89,62.69)
VCC3V3: length 40
  TOP w0.191: v1(25.16,59.83) 24.34,59.83 C56.1
  BOTTOM w0.254: J4.37 10.03,64.97 10.3,64.71 10.06,64.47 J4.36
  BOTTOM w0.305: R50.1 R51.1 R67.1 R69.1 v1(20.25,66.39) ; U6.25 v1(25.16,59.83) ; U6.3 v1(17.65,58.33) ; U6.30 24.61,57.33 24.75,57.19 v1(24.75,56.66) ; v1(27.98,53.83) R64.1 R70.1 R71.1 R72.1 R73.1 R66.1 R68.1 R74.1 R49.1 R48.1 ; v1(25.95,65.73) R62.1 R60.1 R53.1 ; v1(21.18,64.48) C55.1 21.1,63.64 U6.15 ; U7.8 25.64,49.26 26.13,48.77 C57.1 27.57,48.77 C58.1 v1(28.6,48.92) ; U6.8 v1(17.61,60.83) ; C11.1 176.57,45.14 J9.5
  BOTTOM w0.457: R13.1 v1(83.74,48.13) ; R27.1 97.86,55.25 v1(97.77,55.16) ; v1(13.46,64.69) C25.1 12.56,64.54 C26.1 10.46,64.54 10.3,64.71 ; R12.1 v1(83.74,50.41) ; R40.1 v1(125.48,51.25) ; v1(176.81,44.15) C11.1 ; R11.1 v1(83.74,51.55)
  vias: v1(14.46,64.71) v1(15.38,64.71) v1(72.02,52.65)
VCC_5V0: length 14.2
  BOTTOM w0.191: U2.3 v1(73.45,68.74)
  BOTTOM w0.254: 90.21,67.25 90.21,66.2 90.64,65.78 U3.2
  BOTTOM w0.305: U5.4 133.25,59.86
  BOTTOM w0.457: R20.1 v1(80.36,66.19) ; v1(89.31,67.25) 90.21,67.25 ; v1(121.31,62.81) 121.31,62.21 C47.1 ; R23.1 v1(89.55,68.78) ; L3.1 v1(139.07,62.11) ; v1(70.77,69.82) C29.1 71.55,67.77 ; 73.45,67.77 v1(73.45,68.74)
  vias: v1(10.75,65.73) v1(11.77,65.73) v1(12.78,66.64) v1(12.78,65.73) v1(69.83,68.78) v1(69.86,69.82) v1(70.75,68.78) v1(88.4,68.78) v1(88.39,67.25) v1(137.93,62.96) v1(137.93,62.04) v1(139.07,63.02)
VDD_2V5:
  vias: v1(43.7,56.58) v1(44.71,56.58) v1(75.19,60.02) v1(75.19,59.11)
VDD_OPT: length 5.5
  BOTTOM w0.191: R19.2 R20.2 78.68,65.21 78.53,65.36 78.53,67.16 TP7.1
ADJ: length 3.9
  BOTTOM w0.191: C50.2 124.29,52.94 123.8,53.43 123.8,55.1 124.02,55.31 U5.14
BKLT_L: length 1.2
  BOTTOM w0.305: U3.1 90.14,64.95 89.62,65.47 89.42,65.47
BKLT_SW: length 0.9
  BOTTOM w0.305: U3.10 90.14,61.49 89.67,61.03
BRDID_EEPROM_A0: length 90.1
  TOP w0.191: v1(81.33,52.7) 80.48,51.84 80.48,45.71 v1(81.67,44.52)
  BOTTOM w0.191: J4.10 11.56,51.47 13.8,49.24 17.02,49.24 21.74,44.52 v1(81.67,44.52) ; v1(81.33,52.7) R17.1 R11.2 U1.1
BRDID_EEPROM_A1: length 87.7
  TOP w0.191: v1(81.33,49.27) 80.86,48.79 80.86,46.4 v1(82.74,44.52)
  BOTTOM w0.191: v1(81.33,49.27) R16.1 R12.2 81.47,50.41 81.34,50.28 U1.2 ; J4.7 11.75,49.97 12.87,48.86 16.86,48.86 21.71,44.01 82.23,44.01 v1(82.74,44.52)
BRDID_EEPROM_A2: length 86.5
  TOP w0.191: v1(81.33,46.98) 83.4,44.92 83.4,44.86 v1(83.74,44.52)
  BOTTOM w0.191: U1.3 79.89,49.01 80.78,48.13 R13.2 R15.1 v1(81.33,46.98) ; J4.4 16.7,48.47 21.55,43.63 82.85,43.63 v1(83.74,44.52)
COMP: length 3
  BOTTOM w0.305: U5.22 123.13,60.51 122.87,60.76 C51.1
CPI: length 22.7
  TOP w0.305: v1(129.52,48.64) 122.94,48.64 121.46,50.11 v1(121.46,54.74)
  BOTTOM w0.254: R115.2 v1(129.52,48.64)
  BOTTOM w0.305: U5.16 123.54,56.61 122.81,55.88 120.84,55.88 120.56,55.6 C60.1 ; C60.1 v1(121.46,54.74) ; C60.1 D4.2
CPI_1: length 10.7
  BOTTOM w0.254: D4.1 114.67,53.09 112.81,54.95 C46.1 D3.2
CTRL: length 3.4
  BOTTOM w0.191: U5.13 124.51,54.66 124.21,54.36 124.21,53.72 124.41,53.52 124.86,53.52 125.44,52.94 R40.2
DLY1: length 2.1
  BOTTOM w0.191: C54.2 U5.2
DLY2: length 3.5
  BOTTOM w0.191: U5.3 133.36,60.51 134.01,61.16 C53.2
ECAP0_IN_APWM0_OUT: length 114.7
  TOP w0.191: v1(99.57,54.5) 99.57,45.78 97.67,43.88 v1(96.66,43.88) 96.32,44.22 84.11,44.22 83.93,44.04 80.87,44.04 80.09,44.81 21.95,44.81 16.73,50.04 13.27,50.04 11.79,48.56 10.88,48.56 v1(10.3,47.97)
  BOTTOM w0.191: J4.3 v1(10.3,47.97)
  BOTTOM w0.305: Q1.1 101.59,57.31 99.57,55.29 R27.2 v1(99.57,54.5)
EEPROM_WP: length 2.1
  BOTTOM w0.191: R14.2 73.13,50.43 U1.7
EQ0: length 4.2
  TOP w0.191: R54.1 v1(16.7,55.34)
  BOTTOM w0.191: U6.40 19.1,56.31 18.82,56.02 17.23,56.02 16.7,55.49 v1(16.7,55.34) R54.1
EQ1: length 3.7
  TOP w0.191: R55.1 v1(17.84,55.34)
  BOTTOM w0.191: R55.1 v1(17.84,55.34) 18.09,55.59 19.22,55.59 19.6,55.97 U6.39
EQ2: length 4.6
  TOP w0.191: R56.1 v1(16.82,63.97)
  BOTTOM w0.191: U6.11 19.1,62.97 18.85,63.21 17.58,63.21 v1(16.82,63.97) R56.1
EQ3: length 4.2
  TOP w0.191: R57.1 v1(17.97,63.97)
  BOTTOM w0.191: R57.1 v1(17.97,63.97) 18.92,63.97 19.6,63.29 U6.12
FBN: length 23.7
  BOTTOM w0.191: U5.21 123.13,59.86 122.97,60.01 119.77,60.01 114.18,65.6 111.64,65.6 110.75,64.71 110.75,60.48 110.94,60.29 R36.2 R39.1
FDLY: length 3.2
  BOTTOM w0.305: C47.2 122.87,62.06 123.13,61.81 U5.24
GD: length 23.3
  TOP w0.191: v1(142.01,64.46) 142.01,63.4 139.45,60.84 131.26,60.84 129.87,62.23 125.04,62.23 v1(123.97,61.16)
  BOTTOM w0.191: U5.23 v1(123.97,61.16) ; R37.2 v1(142.01,64.46)
LCD_BACKLIGHT_EN: length 93.5
  TOP w0.191: v1(10.3,51.97) 17.65,51.97 22.51,47.11 59.11,47.11 68.16,56.15 89.8,56.15 v1(93.02,59.38)
  BOTTOM w0.191: v1(93.02,59.38) R30.1 93.02,60.18 92.14,61.07 U3.6 ; J4.11 v1(10.3,51.97)
LCD_BRD_DET: length 1.9
  BOTTOM w0.191: J4.1 R18.2
LCD_BRD_TOUCH_INT: length 178.3
  BOTTOM w0.191: J4.12 11.1,52.47 13.95,49.62 17.2,49.62 21.62,45.2 99.15,45.2 104.51,50.56 109.7,50.56 116.28,43.99 157.72,43.99 TP30.1 162.26,44.06 174.91,44.06 176.07,45.22 J9.4
LCD_BRD_TOUCH_RESETN: length 174
  TOP w0.191: v1(11.31,48) 11.87,48 13.53,49.66 16.57,49.66 22,44.23 80.14,44.23 80.71,43.66 84.09,43.66 84.27,43.84 96.03,43.84 96.94,42.93 112.56,42.93 114.77,45.13 v1(162.57,45.13)
  BOTTOM w0.191: v1(162.57,45.13) TP29.1 164.09,44.77 174.76,44.77 175.57,45.58 175.57,46.45 ; J4.2 10.56,47.47 10.74,47.66 10.97,47.66 v1(11.31,48)
LCD_SHIELD: length 7.5
  BOTTOM w0.457: J4.SH1 9.41,45.98 9.41,44.39 8.89,43.87 J4.SH3 ; J10.41 41.04,63.62 40.58,63.16 39.71,63.16 39.51,62.96 FL1.2
LED+: length 32.9
  L02_PWR w0.457: TP32.1 83.19,61.92 v1(62.24,61.92) v1(61.32,61.92)
  BOTTOM w0.457: TP32.1 C32.1 90.62,58.35 90.63,58.36 R21.2
LED-: length 49.4
  TOP w0.305: v1(57.67,62.04) v1(58.68,62.04)
  L02_PWR w0.457: TP33.1 96.07,58.62 90.43,58.62 86.37,62.68 60.33,62.68 59.7,62.04 v1(58.68,62.04) v1(57.67,62.04)
  BOTTOM w0.457: R24.2 TP33.1
LOSN0: length 2.3
  BOTTOM w0.191: R69.2 20.25,64.03 20.6,63.68 U6.14
LOSN1: length 2
  BOTTOM w0.191: R68.2 20.16,54.81 20.6,55.25 U6.37
LOSN2: length 1.8
  BOTTOM w0.191: U6.36 21.1,55.56 21.22,55.44 R66.2
LOSN3: length 2.6
  BOTTOM w0.191: R67.2 19.11,64.48 20.1,63.49 U6.13
OLDI0_A0N: length 6.8
  BOTTOM w0.127: J4.33 10.06,62.97 10.16,62.88 13.15,62.88 13.6,62.43 15.45,62.43 R102.1
OLDI0_A0N_R: length 37.3
  BOTTOM w0.127: J10.8 46.44,59.53 46.54,59.43 46.54,57.81 46.73,57.61 46.73,54.27 46.61,54.14 39.99,54.14 39.84,54.3 39.84,60.47 39.4,60.9 35.27,60.9 34.97,60.6 34.97,59.02 34.84,58.89 34.59,58.89 34.46,59.02 34.46,60.6 34.16,60.9 30.34,60.9 28.68,62.55 26.93,62.55 26.8,62.68 R109.2
OLDI0_A0P: length 6.8
  BOTTOM w0.127: J4.32 10.06,62.47 10.16,62.57 13.02,62.57 13.47,62.12 15.43,62.12 R101.1
OLDI0_A0P_R: length 37.5
  BOTTOM w0.127: J10.9 46.94,59.53 46.84,59.43 46.84,57.93 47.04,57.74 47.04,54.15 46.73,53.84 39.86,53.84 39.53,54.17 39.53,60.34 39.28,60.6 35.4,60.6 35.27,60.47 35.27,58.9 34.97,58.59 34.46,58.59 34.16,58.9 34.16,60.47 34.03,60.6 30.21,60.6 28.56,62.25 27.01,62.25 26.83,62.07 26.81,62.07 R110.2
OLDI0_A1N: length 6.9
  BOTTOM w0.127: J4.30 10.06,61.47 10.16,61.38 12.77,61.38 13.5,60.65 15.45,60.65 R100.1
OLDI0_A1N_R: length 38
  BOTTOM w0.127: R108.2 26.8,60.9 26.93,60.77 28.43,60.77 33.76,55.44 37.23,55.44 37.42,55.64 37.42,57.45 37.73,57.75 38.26,57.75 38.57,57.45 38.57,53.43 39.3,52.7 47.48,52.7 48.38,53.59 48.38,54.19 48.04,54.53 48.04,59.43 47.94,59.53 J10.11
OLDI0_A1P: length 6.9
  BOTTOM w0.127: J4.29 10.06,60.97 10.16,61.07 12.64,61.07 13.37,60.34 15.41,60.34 15.72,60.04 R99.1
OLDI0_A1P_R: length 38.3
  BOTTOM w0.127: J10.12 48.44,59.53 48.34,59.43 48.34,54.65 48.68,54.32 48.68,53.47 47.61,52.39 39.18,52.39 38.26,53.31 38.26,57.32 38.13,57.45 37.85,57.45 37.73,57.32 37.73,55.51 37.35,55.14 33.64,55.14 28.3,60.47 26.99,60.47 26.81,60.29 R107.2
OLDI0_A2N: length 7
  BOTTOM w0.127: J4.27 10.06,59.97 10.16,59.88 12.28,59.88 13.32,58.84 15.43,58.84 R98.1
OLDI0_A2N_R: length 38
  BOTTOM w0.127: R106.2 26.8,59.12 26.93,59 28.05,59 34.76,52.29 35.98,52.29 36.12,52.44 36.12,53.69 36.43,53.99 36.94,53.99 37.24,53.69 37.24,51.51 37.47,51.27 47.84,51.27 49.64,53.07 49.64,59.33 49.44,59.53 J10.14
OLDI0_A2P: length 7
  BOTTOM w0.127: R97.1 15.72,58.26 15.44,58.54 13.19,58.54 12.16,59.57 10.16,59.57 10.06,59.47 J4.26
OLDI0_A2P_R: length 38.2
  BOTTOM w0.127: R105.2 26.98,58.69 27.92,58.69 34.63,51.99 36.1,51.99 36.43,52.31 36.43,53.56 36.55,53.69 36.81,53.69 36.94,53.56 36.94,51.38 37.35,50.97 47.96,50.97 49.94,52.95 J10.15
OLDI0_A3N: length 7.1
  BOTTOM w0.127: J4.24 10.06,58.47 10.16,58.38 11.75,58.38 13.04,57.09 15.45,57.09 R96.1
OLDI0_A3N_R: length 37.3
  BOTTOM w0.127: R104.2 26.8,57.37 26.93,57.24 27.72,57.24 35.06,49.9 48.24,49.9 52.64,54.29 52.64,59.33 52.44,59.53 J10.20
OLDI0_A3P: length 7.1
  BOTTOM w0.127: R95.1 15.43,56.79 12.91,56.79 11.63,58.07 10.16,58.07 10.06,57.97 J4.23
OLDI0_A3P_R: length 37.5
  BOTTOM w0.127: J10.21 52.94,54.17 48.37,49.6 34.93,49.6 27.59,56.94 27.01,56.94 R103.2
OLDI0_CLKN: length 14.4
  BOTTOM w0.127: J4.21 9.9,56.97 10,56.88 11.2,56.88 15.58,52.49 18.55,52.49 20.33,50.72 20.71,50.72 R112.1
OLDI0_CLKN_R: length 32.7
  TOP w0.127: v1(50.73,54.17) 51.01,54.17 51.14,54.04 51.14,53.86 50.05,52.77 30.62,52.77 28.81,50.97 28.38,50.97 v1(28.1,51.25)
  BOTTOM w0.127: v1(50.73,54.17) 50.96,54.17 51.11,54.32 51.11,54.5 51.04,54.58 51.04,59.43 50.94,59.53 J10.17 ; v1(28.1,51.25) 28.1,51.2 27.83,50.93 27.65,50.93 R114.2
OLDI0_CLKP: length 14.4
  BOTTOM w0.127: J4.20 9.96,56.47 10.06,56.57 11.07,56.57 15.45,52.19 18.42,52.19 20.2,50.41 20.68,50.41 R111.1
OLDI0_CLKP_R: length 32.7
  TOP w0.127: v1(28.1,50.36) 28.41,50.67 28.94,50.67 30.74,52.47 50.17,52.47 51.44,53.74 51.44,53.97 v1(51.65,54.17)
  BOTTOM w0.127: J10.18 51.44,59.53 51.34,59.43 51.34,54.75 51.42,54.67 51.42,54.4 v1(51.65,54.17) ; v1(28.1,50.36) 27.83,50.63 27.61,50.63 R113.2
PE0: length 4.9
  TOP w0.191: R65.1 v1(26.98,55.34)
  BOTTOM w0.191: U6.31 24.16,56.58 24.55,56.18 25.38,56.18 25.87,55.69 26.63,55.69 v1(26.98,55.34) R65.1
PE1: length 3.6
  TOP w0.191: R63.1 v1(24.95,63.97)
  BOTTOM w0.191: R63.1 v1(24.95,63.97) 24.18,63.21 23.97,63.21 23.6,62.84 U6.20
PE2: length 3.3
  TOP w0.191: R61.1 v1(23.81,63.97)
  BOTTOM w0.191: U6.19 23.1,63.27 v1(23.81,63.97) R61.1
PE3: length 3
  TOP w0.191: R59.1 v1(22.66,63.97)
  BOTTOM w0.191: U6.18 22.6,63.91 v1(22.66,63.97) R59.1
PWDNN: length 2.3
  BOTTOM w0.191: R74.2 19.02,54.81 20.1,55.89 U6.38
PWDNN0: length 2
  BOTTOM w0.191: U6.35 21.6,55.47 R73.2
PWDNN1: length 2.5
  BOTTOM w0.191: R72.2 23.36,55.01 23.08,55.01 22.1,55.99 U6.34
PWDNN2: length 3.1
  BOTTOM w0.191: R71.2 24.66,54.81 24.06,55.41 23.21,55.41 22.6,56.03 U6.33
PWDNN3: length 3.8
  BOTTOM w0.191: R70.2 25.8,54.81 24.81,55.8 23.37,55.8 23.1,56.08 U6.32
REF: length 18.3
  BOTTOM w0.191: R39.2 C52.1 111.77,64.67 112.19,65.09 113.95,65.09 119.41,59.63 122.56,59.63 122.99,59.21 U5.20
SOC_I2C1_SCL: length 181
  BOTTOM w0.191: J4.15 10.94,53.97 14.53,50.39 17.6,50.39 21.76,46.23 98.82,46.23 104.14,51.55 110.02,51.55 116.71,44.87 153.52,44.87 TP28.1 160.03,51.38 174.13,51.38 175.07,50.43 J9.2
SOC_I2C1_SDA: length 180
  BOTTOM w0.191: J4.14 10.64,53.47 14.11,50 17.42,50 21.64,45.79 98.92,45.79 104.23,51.1 109.94,51.1 116.55,44.49 155.68,44.49 TP27.1 162.06,50.87 173.87,50.87 174.57,50.17 J9.1
SOC_SPI1_CLK: length 96.3
  TOP w0.191: J11.2 94.88,50.87 91.07,54.68 69.16,54.68 60.45,45.97 22.42,45.97 17.21,51.18 12.17,51.18 11.37,50.38 10.89,50.38 v1(10.3,50.97)
  BOTTOM w0.191: J4.9 v1(10.3,50.97)
SOC_SPI1_CS0: length 97.9
  TOP w0.191: v1(11.31,51) 11.88,51.56 17.36,51.56 22.58,46.35 60.29,46.35 69,55.06 91.58,55.06 97.42,49.22 J11.1
  BOTTOM w0.191: J4.8 10.79,50.47 v1(11.31,51)
SOC_SPI1_MISO: length 94.7
  TOP w0.191: J11.3 92.34,52.52 90.56,54.3 69.32,54.3 60.61,45.59 22.26,45.59 17.05,50.8 12.62,50.8 v1(11.31,49.5)
  BOTTOM w0.191: v1(11.31,49.5) 10.79,48.97 J4.5
SOC_SPI1_MOSI: length 92.3
  TOP w0.191: J11.4 89.8,52.77 88.65,53.92 69.48,53.92 60.76,45.2 22.1,45.2 16.89,50.42 13.07,50.42 11.59,48.94 10.83,48.94 v1(10.3,49.47)
  BOTTOM w0.191: J4.6 v1(10.3,49.47)
SOC_WKUP_SCL: length 68.3
  BOTTOM w0.191: U1.6 71.31,49.01 69.35,47.06 22,47.06 17.92,51.15 14.85,51.15 10.52,55.47 J4.18
SOC_WKUP_SDA: length 67.8
  BOTTOM w0.191: U1.5 71.08,47.74 70.01,46.68 21.85,46.68 17.76,50.77 14.69,50.77 10.48,54.97 J4.17
SW: length 19.8
  TOP w0.305: v1(132.09,58.87) 130.81,57.59 130.81,50.85 129.24,49.28 v1(123.88,49.28)
  BOTTOM w0.305: U5.5 131.75,59.21 v1(132.09,58.87) 131.78,58.56 U5.6 ; C59.1 v1(123.88,49.28)
VCOM: length 113
  TOP w0.305: v1(133.89,55.21) 135.42,55.21 136.65,53.98 TP8.1
  L02_PWR w0.457: v1(133.89,55.21) 131.96,53.28 88.91,53.28 88.3,53.89 69.32,53.89 66.56,51.12 60.59,51.12 55.13,56.58 48.01,56.58 47.12,55.69 43.06,55.69 v1(41.9,56.85)
  BOTTOM w0.305: U5.10 C49.1 ; J10.1 42.94,59.26 42.43,58.74 C13.1 41.88,57.62 C19.1 v1(41.9,56.85)
  BOTTOM w0.457: C49.1 v1(133.89,55.21)
VGH: length 75.2
  L02_PWR w0.457: v1(62.75,54.3) v1(62.75,53.38) 66.15,53.38 68.46,55.69 88.15,55.69 90.18,57.73 104.46,57.73 TP10.1 106.8,60.07 118.3,60.07 122.68,55.69 v1(122.68,55.08)
  BOTTOM w0.305: C48.1 122.85,53.86 123.22,54.23 123.22,55.52 123.65,55.96 U5.15 ; J10.38 61.44,58.96 63.02,57.38
  BOTTOM w0.457: C48.1 v1(122.68,55.08)
VGL: length 61.4
  L02_PWR w0.457: TP9.1 106.75,56.96 90.56,56.96 88.4,54.81 68.84,54.81 66.56,52.52 61.58,52.52 v1(60.71,53.38) v1(60.71,54.3)
  BOTTOM w0.305: J10.35 59.94,58.02 59.94,58.02 C16.1
  BOTTOM w0.457: TP9.1 R36.1 C43.1 D2.1
N18700915: length 1.7
  BOTTOM w0.305: R21.1 90.63,60.55 90.64,60.56 U3.9
N18700972: length 5.7
  TOP w0.191: v1(96.66,65.09) 96.66,65.73 96.4,65.98 v1(95.9,65.98) 95.43,65.98 95.3,66.11 v1(92.72,66.11) v1(92.72,65.09)
N18700978: length 9.9
  TOP w0.191: v1(91.08,66.24) 91.08,67.01 92.08,68.01 95.4,68.01 v1(96.03,67.38)
  BOTTOM w0.191: v1(91.08,66.24) 91.08,65.76 91.14,65.7 U3.3 ; R28.1 96.76,67.99 96.74,67.98 R25.1 v1(96.03,67.38)
N18701008: length 2.9
  BOTTOM w0.191: Q1.3 100.06,67.39 100.05,67.38 R25.2
N18701075: length 12.2
  TOP w0.191: v1(91.96,68.78) 89.67,66.49 89.67,61.54 90.43,60.77 v1(91.7,60.77)
  BOTTOM w0.191: R23.2 v1(91.96,68.78) ; U3.7 91.64,60.84 v1(91.7,60.77)
N18704134: length 73
  TOP w0.305: v1(138.95,55.01) 138.95,49.54 137.29,47.88 118.87,47.88 115.07,51.68 v1(115.07,54.04)
  BOTTOM w0.305: R33.1 139.46,69.26 C37.1 141.05,69.01 U4.2 142.07,68.96 142.38,68.66 142.38,67.38 143.84,65.91 145.54,65.91 145.92,65.54 R34.1 145.92,64.18 C40.1 146.32,63.47 C42.1 146.32,59.92 D1.1 147.37,56.47 146.27,55.37 C38.1 145.89,55.15 C39.1 139.62,55.15 139.48,55.01 v1(138.95,55.01) R32.2 136.79,55.82 135.77,56.84 133.49,56.84 133.26,56.61 U5.9 ; D3.1 v1(115.07,54.04)
N18704138: length 6.3
  BOTTOM w0.305: C40.2 144.94,64.18 R34.2 143.75,65.17 143.63,65.3 R37.1 142.99,66.04 141.96,67.06 U4.1
N18704166: length 13.6
  TOP w0.305: v1(132.09,61.81) 132.09,64.71 133.37,65.99 136.01,65.99 v1(137.03,67.01)
  BOTTOM w0.305: U5.1 v1(132.09,61.81) ; v1(137.03,67.01) R35.1 138.29,67.76 R33.2 139.46,67.78 C37.2
N18704218: length 3.4
  BOTTOM w0.305: C44.1 119.39,58.74 118.37,59.76 D2.3
N18704228: length 3.5
  BOTTOM w0.305: C45.2 119.42,57.09 118.15,55.82 D3.3
N18704232: length 0.6
  BOTTOM w0.191: 131.42,54.66 U5.12
N18704253: length 3.6
  BOTTOM w0.305: C44.2 122.72,58.74 123.55,57.91 U5.18
N18704306: length 6.9
  BOTTOM w0.305: U5.11 132.6,55.31 133.23,54.68 R31.2 C35.2 C34.2 R32.1
N18704451: length 3.3
  BOTTOM w0.305: U5.17 123.49,57.26 123.33,57.09 C45.1
N18706570: length 1.2
  BOTTOM w0.305: R42.1 120.17,60.76 C51.2
N18754783: length 6.2
  BOTTOM w0.191: R26.1 R22.2 C30.2 ; C33.1 C30.2 ; C30.2 74.64,65.56 74.15,65.07 U2.4
N18830955: length 2.4
  BOTTOM w0.127: U6.1 17.88,57.33 17.79,57.42 17.61,57.42 16.96,56.77 16.68,56.77 R95.2
N18830958: length 2.4
  BOTTOM w0.127: R96.2 16.68,57.08 16.84,57.08 17.48,57.73 17.69,57.73 17.79,57.83 U6.2
N18830961: length 2.3
  BOTTOM w0.127: U6.4 17.91,58.83 17.79,58.95 17.51,58.95 17.13,58.56 16.7,58.56 R97.2
N18830964: length 2.3
  BOTTOM w0.127: R98.2 16.67,58.87 17,58.87 17.38,59.25 17.93,59.25 18,59.33 U6.5
N18830967: length 2.3
  BOTTOM w0.127: R99.2 16.44,60.04 16.77,60.37 16.95,60.37 17.41,59.91 17.92,59.91 18,59.83 U6.6
N18830970: length 2.3
  BOTTOM w0.127: U6.7 17.9,60.33 17.79,60.22 17.53,60.22 17.08,60.67 16.7,60.67 16.44,60.93 R100.2
N18830973: length 2.4
  BOTTOM w0.127: U6.9 18.1,61.33 18,61.43 17.63,61.43 16.91,62.15 16.72,62.15 R101.2
N18830976: length 2.4
  BOTTOM w0.127: U6.10 18.03,61.83 17.93,61.73 17.75,61.73 17.04,62.45 16.64,62.45 R102.2
N18831695: length 2.6
  BOTTOM w0.127: R103.1 26.14,56.76 25.99,56.91 25.61,56.91 25.28,57.25 25.28,57.75 25.1,57.93 24.45,57.93 U6.29
N18831698: length 2.9
  BOTTOM w0.127: R104.1 26.14,57.35 26.02,57.22 25.74,57.22 25.59,57.37 25.59,57.88 25.23,58.23 24.44,58.23 U6.28
N18831701: length 1.9
  BOTTOM w0.127: R105.1 25.87,58.79 24.39,58.79 U6.27
N18831704: length 2.1
  BOTTOM w0.127: R106.1 26.14,59.33 25.92,59.1 25.1,59.1 24.87,59.33 U6.26
N18831707: length 1.8
  BOTTOM w0.127: R107.1 26.07,60.37 25.07,60.37 25.03,60.33 U6.24
N18831710: length 2.1
  BOTTOM w0.127: U6.23 25.03,60.83 25.18,60.67 25.64,60.67 R108.1
N18831713: length 2.5
  BOTTOM w0.127: R110.1 25.97,62.25 25.71,62.25 25.59,62.12 25.59,61.73 25.28,61.42 24.94,61.42 24.84,61.33 U6.22
N18831716: length 2.7
  BOTTOM w0.127: R109.1 26.14,62.68 26.02,62.55 25.59,62.55 25.28,62.25 25.28,61.86 25.15,61.73 24.91,61.73 24.81,61.83 U6.21
N18844920: length 1.2
  BOTTOM w0.127: U7.7 26.15,50.29 26.37,50.51 26.53,50.51 R113.1
N18844923: length 1.2
  BOTTOM w0.127: R114.1 26.22,50.79 U7.6
N18844960: length 1.1
  BOTTOM w0.127: R111.2 21.83,50.29 U7.2
N18844963: length 1.1
  BOTTOM w0.127: U7.3 21.86,50.79 R112.2
N18857919: length 2
  BOTTOM w0.254: R115.1 129.52,52.03 130.08,52.6 R38.2
N18858160: length 2.9
  BOTTOM w0.305: D4.3 119.61,49.93 120.26,49.28 C59.2

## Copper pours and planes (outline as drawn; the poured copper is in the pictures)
DGND on TOP: 1.02,42.8 1.02,70.71 194.16,70.71 194.16,42.8
DGND on BOTTOM: 194.16,42.77 10.73,42.77 10.73,70.68 194.16,70.68 ; 12 cut-outs
DGND on BOTTOM: 8.64,63.95 8.64,63.19 15.63,63.19 15.63,63.95
DGND on L02_PWR: 28.56,49.85 51.87,49.85 52.31,50.28 52.31,55.21 52.08,55.44 47.96,55.44 47.38,54.86 37.7,54.86 37.52,54.68 29.83,54.68 26.63,51.48 26.63,49.98 27.06,49.55 28.25,49.55
DGND on L03_GND: 1.04,42.77 1.04,70.68 194.14,70.68 194.14,42.77
VCC3V3 on BOTTOM: 70.77,53.66 70.77,51.05 74.33,51.05 74.33,52.19 73.67,52.19 73.67,53.66
VCC3V3 on BOTTOM: 8.77,65.22 8.77,64.33 15.63,64.33 15.63,65.09 14.23,65.09 14.23,65.22
VCC3V3 on L02_PWR: 1.28,64.97 1.28,42.87 194.13,42.87 194.13,58.11 77.61,58.11 77.61,55.06 36.46,55.06 36.2,55.31 36.2,61.28 35.95,61.54 34.04,61.54 29.01,66.57 17.28,66.57 15.68,64.97 ; 4 cut-outs
VCC_5V0 on BOTTOM: 129.93,60.52 129.93,59.71 132.09,59.71 132.16,59.63 140.09,59.63 140.09,63.31 137.68,63.31 137.68,60.9 135.01,60.9 135.01,60.52
VCC_5V0 on BOTTOM: 69.6,70.3 69.6,67.12 71.89,67.12 71.89,70.3
VCC_5V0 on BOTTOM: 8.64,66.62 8.64,65.3 9.99,65.3 10.17,65.47 13.72,65.47 13.72,66.87 12.2,66.87 11.95,66.62
VCC_5V0 on BOTTOM: 88.15,69.41 88.15,66.62 90.86,66.62 90.86,69.41
VCC_5V0 on L02_PWR: 15.6,65.47 1.28,65.47 1.28,70.68 194.16,70.68 194.16,58.74 77.48,58.74 77.48,62.3 34.5,62.3 29.78,67.02 17.15,67.02 ; 4 cut-outs
VDD_2V5 on BOTTOM: 73.34,63.82 73.34,58.55 75.7,58.55 75.7,62.3 80.04,62.3 80.04,63.57 77.61,63.57 77.61,64.94 75.4,64.94 75.4,63.82
VDD_2V5 on BOTTOM: 43.19,61.21 43.19,56.38 43.29,56.28 44.84,56.28 44.97,56.41 44.97,56.94 44.18,56.94 44.18,61.21
VDD_2V5 on L02_PWR: 36.97,55.82 76.97,55.82 76.97,61.54 36.97,61.54 ; 1 cut-out
BKLT_L on BOTTOM: 83.32,66.24 83.32,63.7 88.4,63.7 88.91,64.2 90.43,64.2 90.43,66.24
BKLT_SW on BOTTOM: 83.45,62.81 83.45,60.52 90.31,60.52 90.31,62.81
LCD_SHIELD on BOTTOM: 1.44,42.99 1.44,70.68 66.05,70.68 66.05,62.04 63.25,62.04 63.25,63.44 42.17,63.44 42.17,62.73 36.46,62.73 36.46,69.28 10.04,69.28 10.04,42.99
LED+ on BOTTOM: 61.73,59.63 61.73,61.41 60.97,61.41 60.97,62.43 62.62,62.43 62.62,59.63
LED- on BOTTOM: 57.67,59.63 57.67,61.41 57.29,61.41 57.29,62.43 58.94,62.43 58.94,61.41 58.68,61.41 58.68,59.63
SW on BOTTOM: 130.03,59.41 130.03,58.36 136.41,58.36 137.8,56.96 144.28,56.96 144.28,60.9 141.49,60.9 141.49,59.12 132.41,59.12 132.13,59.41
VCOM on BOTTOM: 41.54,59.12 41.54,56.46 42.43,56.46 42.43,59.12
VGH on BOTTOM: 61.98,57.98 61.98,53.03 63.38,53.03 63.38,57.98
VGL on BOTTOM: 59.57,57.98 59.57,53.03 61.48,53.03 61.48,57.98
N18700972 on BOTTOM: 91.96,66.36 91.96,64.2 92.72,64.2 92.72,64.33 92.97,64.33 92.97,66.36
N18700972 on BOTTOM: 95.64,66.36 95.64,65.35 96.15,65.35 96.15,63.95 97.04,63.95 97.04,66.36
N18704232 on BOTTOM: 130.06,54.93 130.06,53.66 130.95,53.66 130.95,50.8 131.95,50.8 131.95,54.93
N18754754 on BOTTOM: 70.65,66.06 70.65,61.03 72.35,61.03 72.35,66.06

Small or netless copper shapes (teardrops, artwork), in the pictures only: 59 on TOP, 84 on BOTTOM, 5 on L02_PWR

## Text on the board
Ref Des/Assembly Bottom: AM654x Rocktech RK101II01D LCD Adapter Board Bottom Assembly
Ref Des/Silkscreen Bottom: LCD-CON | SPI | CTP-CON
User.Comments: BOARD NAME: | AM654x Rocktech RK101II01D LCD Adapter Board | REV: E3 | DATE: 03/07/2018 | DESCRIPTION: | SHEET | OF | 11 | PROC070 | SCALE: 1 | TEXAS INSTRUMENTS
Ref Des/Assembly Top: AM654x Rocktech RK101II01D LCD Adapter Board Top Assembly
Ref Des/Silkscreen Top: For Evaluation only; not FCC approved for resale | PROC070 | ASSM P/N:4P0074 | ASSM REV: 1.0 | AM654x Rocktech RK101II01D LCD Adapter Board | PCB Number:3P0009 | PCB Revision:E3 | OPN# | SL#
PAGE_OUTLINE: APPROVED BY | LAYOUT BY | REVIEWED BY | SIGNATURES | AMB | VJC | ZA | 030918 | DATE | AM654x Rocktech RK101II01D LCD Adapter Board | SIZE | SCALE: | D | TEXAS INSTRUMENTS | NONE | SHEET 1 OF 11 | PROC070 | Rev | E3
DIMENSION: 30 | 3.20 | dia | 230
DISPLAY_BOTTOM: 11. | 12. | 15. | PCB SHALL BE MANUFACTURED USING IT180A OR EQUIVALENT WITH Er 4. | ALL VIA'S SHALL BE TENTED UNLESS OTHERWISE SPECIFIED. | TRACE IMPEDANCE SHALL BE +/-10% AS-PER IMPEDANCE SPECIFICATION TABLE. | ALL NON FUNCTIONAL PAD'S OF VIA'S AND PTH HOLES SHALL BE REMOVED. | COPY OF LCD ADAPTER | LCD ADAPTER
User.6: PRIMARY-PASTEMASK | 10
User.7: SECONDARY-PASTEMASK | 11
User.8: SECONDARY-SOLDERMASK | 08
User.9: SECONDARY-SILKSCREEN | 09
User.10: SECONDARY-SIDE-SIG | 07
User.26: GROUND-PLANE | 06
User.28: PRIMARY-SIDE-SIG | 04
User.29: POWER-PLANE | 05
User.30: PRIMARY-SILKSCREEN | 02
User.31: PRIMARY-SOLDERMASK | 03
User.32: 02 | L4 | 5 | 7 | 100 | L3
User.35: FIGURE | SIZE | 8.0 | 12.0 | 40.0 | 32.0 | 126.0 | DRILL CHART: TOP to BOTTOM | ALL UNITS ARE IN MILS | TOLERANCE | +3.0/-3.0 | PLATED | NON-PLATED | QTY | 294 | 5 | 16 | 36 | 10
